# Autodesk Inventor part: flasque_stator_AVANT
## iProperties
Created: 2011-01
Part Number: flasque_stator_AVANT
Document SubType Name: Modeling
Designer: eric
Density: 1 g/cm^3
Mass: 17.3567 g
Surface Area: 58.3922 cm^2
Volume: 17.3567 cm^3
Author: eric
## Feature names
1. Base1
